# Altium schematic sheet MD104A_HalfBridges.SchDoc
size Letter; Date: Not shown in title block; ApprovedBy: Not shown in title block; CheckedBy: Not shown in title block; Author: Not shown in title block; CompanyName: Not shown in title block; Engineer: Not shown in title block; Organization: Not shown in title block; Address1: Not shown in title block; Address2: Not shown in title block; Address3: Not shown in title block; Address4: Not shown in title block; DocumentNumber: 2; Revision: Use project parameter SCH_Rev; SheetNumber: 2; SheetTotal: 5; PageSetup: Record=PageOptions¦CenterHorizontal=True¦CenterVertical=True¦PrintScale=1.00¦XCorrection=1.00¦YCorrection=1.00¦PrintKind=0¦BorderSize=5000000¦LeftOffset=0¦BottomOffset=0¦Orientation=2¦PaperLength=1000¦PaperWidth=1000¦Scale=100¦PaperSource=15¦PrintQuality=600¦MediaType=1¦DitherType=10¦PaperKind=Letter¦PrintScaleMode=1
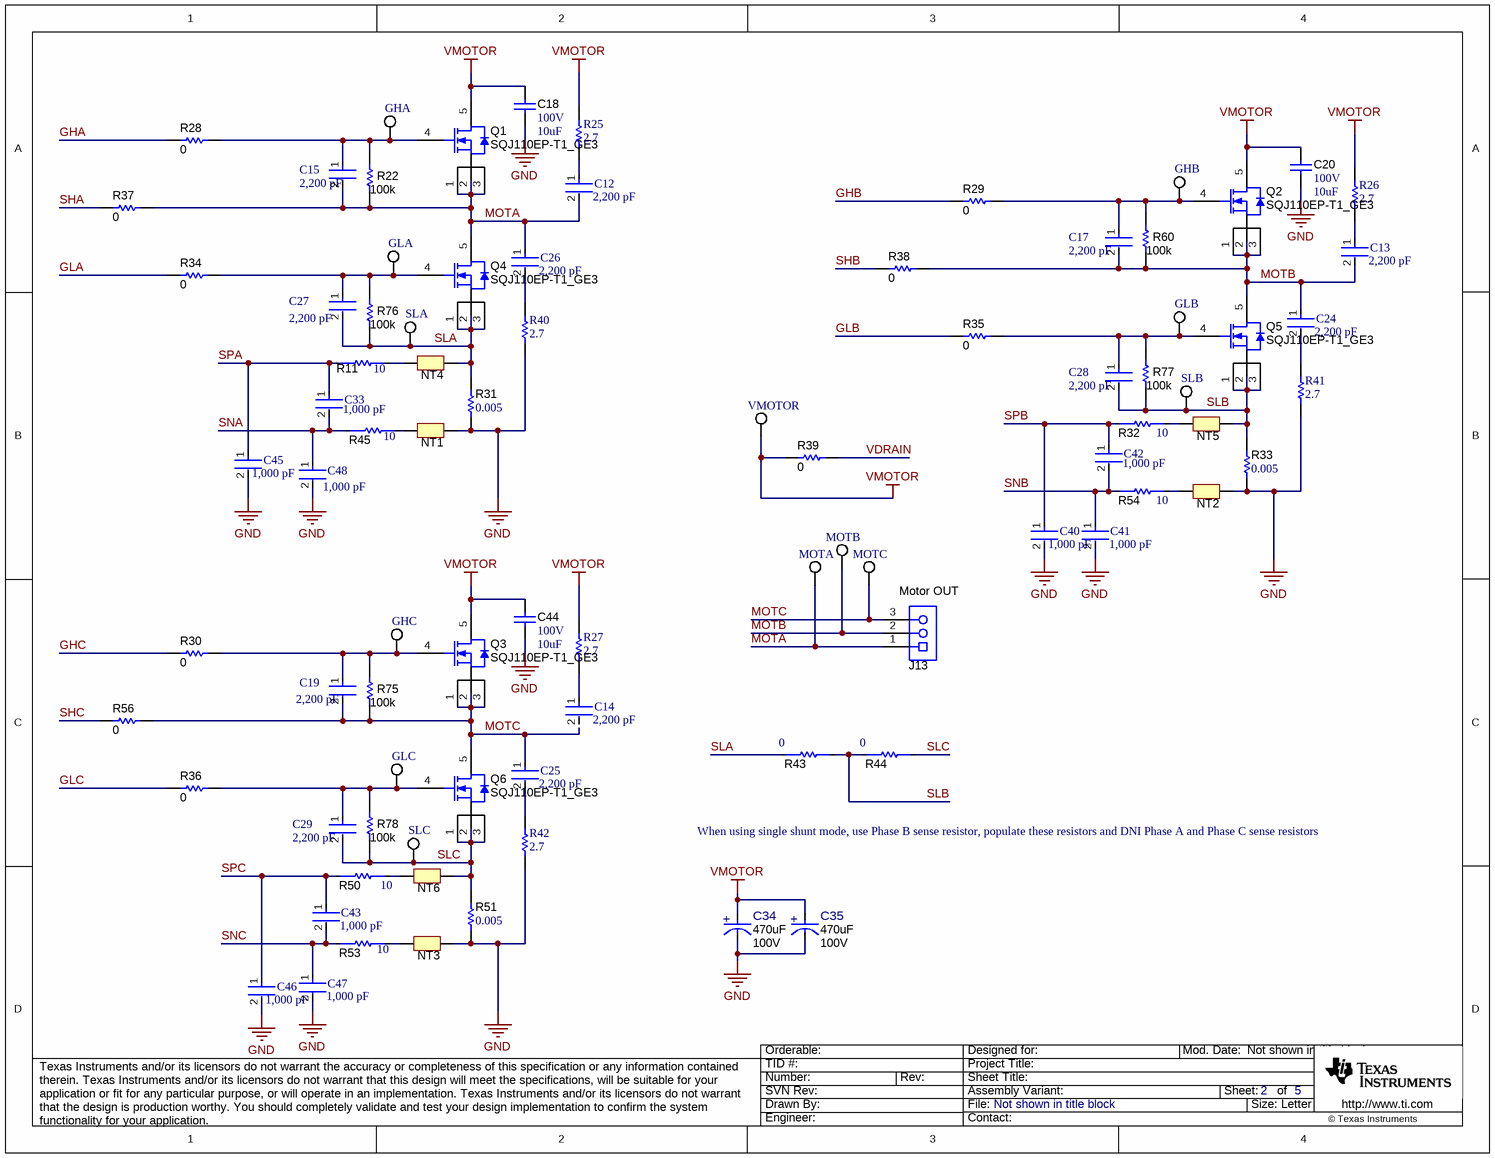
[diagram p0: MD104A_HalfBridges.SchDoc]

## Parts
C12  value 2,200 pF  [FP-C0603C-CF-MFG]  (hidden comment: C0603C222K1RACAUTO)
C13  value 2,200 pF  [FP-C0603C-CF-MFG]  (hidden comment: C0603C222K1RACAUTO)
C14  value 2,200 pF  [FP-C0603C-CF-MFG]  (hidden comment: C0603C222K1RACAUTO)
C15  value 2,200 pF  [FP-C0603C-CF-MFG]  (hidden comment: C0603C222K1RACAUTO)
C17  value 2,200 pF  [FP-C0603C-CF-MFG]  (hidden comment: C0603C222K1RACAUTO)
C18  VDC_V: 100V  ValueDisplayed: 10uF  [2220_280L]  (hidden comment: CGA9N3X7S2A106K230KE)
C19  value 2,200 pF  [FP-C0603C-CF-MFG]  (hidden comment: C0603C222K1RACAUTO)
C20  VDC_V: 100V  ValueDisplayed: 10uF  [2220_280L]  (hidden comment: CGA9N3X7S2A106K230KE)
C24  value 2,200 pF  [FP-C0603C-CF-MFG]  (hidden comment: C0603C222K1RACAUTO)
C25  value 2,200 pF  [FP-C0603C-CF-MFG]  (hidden comment: C0603C222K1RACAUTO)
C26  value 2,200 pF  [FP-C0603C-CF-MFG]  (hidden comment: C0603C222K1RACAUTO)
C27  value 2,200 pF  [FP-C0603C-CF-MFG]  (hidden comment: C0603C222K1RACAUTO)
C28  value 2,200 pF  [FP-C0603C-CF-MFG]  (hidden comment: C0603C222K1RACAUTO)
C29  value 2,200 pF  [FP-C0603C-CF-MFG]  (hidden comment: C0603C222K1RACAUTO)
C33  value 1,000 pF  [FP-C0603C-CF-MFG]  (hidden comment: C0603C102K4RACAUTO)
C34  ValueDisplayed: 470uF  VDC_V: 100V  [FP-ESH477M100AM2AA_RADIAL-MFG]  (hidden comment: ESH477M100AM2AA)
C35  ValueDisplayed: 470uF  VDC_V: 100V  [FP-ESH477M100AM2AA_RADIAL-MFG]  (hidden comment: ESH477M100AM2AA)
C40  value 1,000 pF  [FP-C0603C-CF-MFG]  (hidden comment: C0603C102K4RACAUTO)
C41  value 1,000 pF  [FP-C0603C-CF-MFG]  (hidden comment: C0603C102K4RACAUTO)
C42  value 1,000 pF  [FP-C0603C-CF-MFG]  (hidden comment: C0603C102K4RACAUTO)
C43  value 1,000 pF  [FP-C0603C-CF-MFG]  (hidden comment: C0603C102K4RACAUTO)
C44  VDC_V: 100V  ValueDisplayed: 10uF  [2220_280L]  (hidden comment: CGA9N3X7S2A106K230KE)
C45  value 1,000 pF  [FP-C0603C-CF-MFG]  (hidden comment: C0603C102K4RACAUTO)
C46  value 1,000 pF  [FP-C0603C-CF-MFG]  (hidden comment: C0603C102K4RACAUTO)
C47  value 1,000 pF  [FP-C0603C-CF-MFG]  (hidden comment: C0603C102K4RACAUTO)
C48  value 1,000 pF  [FP-C0603C-CF-MFG]  (hidden comment: C0603C102K4RACAUTO)
GHA  5015  [Testpoint_Keystone_Miniature]  (value not drawn)
GHB  5015  [Testpoint_Keystone_Miniature]  (value not drawn)
GHC  5015  [Testpoint_Keystone_Miniature]  (value not drawn)
GLA  5015  [Testpoint_Keystone_Miniature]  (value not drawn)
GLB  5015  [Testpoint_Keystone_Miniature]  (value not drawn)
GLC  5015  [Testpoint_Keystone_Miniature]  (value not drawn)
J13  Motor OUT  [Phoenix_1904150]
MOTA  5016  [Testpoint_Keystone_Compact]  (value not drawn)
MOTB  5016  [Testpoint_Keystone_Compact]  (value not drawn)
MOTC  5016  [Testpoint_Keystone_Compact]  (value not drawn)
NT1  Net-Tie  [Net-Tie_10mil]  (value not drawn)  (net tie, no BOM)
NT2  Net-Tie  [Net-Tie_10mil]  (value not drawn)  (net tie, no BOM)
NT3  Net-Tie  [Net-Tie_10mil]  (value not drawn)  (net tie, no BOM)
NT4  Net-Tie  [Net-Tie_10mil]  (value not drawn)  (net tie, no BOM)
NT5  Net-Tie  [Net-Tie_10mil]  (value not drawn)  (net tie, no BOM)
NT6  Net-Tie  [Net-Tie_10mil]  (value not drawn)  (net tie, no BOM)
Q1  SQJ110EP-T1_GE3  [PowerPAK_SO-8L]
Q2  SQJ110EP-T1_GE3  [PowerPAK_SO-8L]
Q3  SQJ110EP-T1_GE3  [PowerPAK_SO-8L]
Q4  SQJ110EP-T1_GE3  [PowerPAK_SO-8L]
Q5  SQJ110EP-T1_GE3  [PowerPAK_SO-8L]
Q6  SQJ110EP-T1_GE3  [PowerPAK_SO-8L]
R11  value 10  [FP-CPF-A-0603B10RE_0603-MFG]  (hidden comment: CPF-A-0603B10RE)
R22  ValueDisplayed: 100k  [0603L]  (hidden comment: CRCW0603100KFKEA)
R25  2.7  [RESC1608X55X30LL20T10]
R26  2.7  [RESC1608X55X30LL20T10]
R27  2.7  [RESC1608X55X30LL20T10]
R28  ValueDisplayed: 0  [0603L]  (hidden comment: RCS06030000Z0EA)
R29  ValueDisplayed: 0  [0603L]  (hidden comment: RCS06030000Z0EA)
R30  ValueDisplayed: 0  [0603L]  (hidden comment: RCS06030000Z0EA)
R31  ValueDisplayed: 0.005  [CRE2512-R5_R9]  (hidden comment: CRE2512-FZ-R005E-3)
R32  value 10  [FP-CPF-A-0603B10RE_0603-MFG]  (hidden comment: CPF-A-0603B10RE)
R33  ValueDisplayed: 0.005  [CRE2512-R5_R9]  (hidden comment: CRE2512-FZ-R005E-3)
R34  ValueDisplayed: 0  [0603L]  (hidden comment: RCS06030000Z0EA)
R35  ValueDisplayed: 0  [0603L]  (hidden comment: RCS06030000Z0EA)
R36  ValueDisplayed: 0  [0603L]  (hidden comment: RCS06030000Z0EA)
R37  ValueDisplayed: 0  [0603L]  (hidden comment: RCS06030000Z0EA)
R38  ValueDisplayed: 0  [0603L]  (hidden comment: RCS06030000Z0EA)
R39  ValueDisplayed: 0  [0603L]  (hidden comment: RCS06030000Z0EA)
R40  2.7  [RESC1608X55X30LL20T10]
R41  2.7  [RESC1608X55X30LL20T10]
R42  2.7  [RESC1608X55X30LL20T10]
R43  value 0  [FP-CRCW12060000Z0EAC_1206-MFG]  (hidden comment: CRCW12060000Z0EAC)
R44  value 0  [FP-CRCW12060000Z0EAC_1206-MFG]  (hidden comment: CRCW12060000Z0EAC)
R45  value 10  [FP-CPF-A-0603B10RE_0603-MFG]  (hidden comment: CPF-A-0603B10RE)
R50  value 10  [FP-CPF-A-0603B10RE_0603-MFG]  (hidden comment: CPF-A-0603B10RE)
R51  ValueDisplayed: 0.005  [CRE2512-R5_R9]  (hidden comment: CRE2512-FZ-R005E-3)
R53  value 10  [FP-CPF-A-0603B10RE_0603-MFG]  (hidden comment: CPF-A-0603B10RE)
R54  value 10  [FP-CPF-A-0603B10RE_0603-MFG]  (hidden comment: CPF-A-0603B10RE)
R56  ValueDisplayed: 0  [0603L]  (hidden comment: RCS06030000Z0EA)
R60  ValueDisplayed: 100k  [0603L]  (hidden comment: CRCW0603100KFKEA)
R75  ValueDisplayed: 100k  [0603L]  (hidden comment: CRCW0603100KFKEA)
R76  ValueDisplayed: 100k  [0603L]  (hidden comment: CRCW0603100KFKEA)
R77  ValueDisplayed: 100k  [0603L]  (hidden comment: CRCW0603100KFKEA)
R78  ValueDisplayed: 100k  [0603L]  (hidden comment: CRCW0603100KFKEA)
SLA  5015  [Testpoint_Keystone_Miniature]  (value not drawn)
SLB  5015  [Testpoint_Keystone_Miniature]  (value not drawn)
SLC  5015  [Testpoint_Keystone_Miniature]  (value not drawn)
VMOTOR  5016  [Testpoint_Keystone_Compact]  (value not drawn)

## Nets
GND: C18.2 C20.2 C34.1(CATHODE) C35.1(CATHODE) C40.2 C41.2 C44.2 C45.2 C46.2 C47.2 C48.2 NT1.2 NT2.2 NT3.2 R31.1 R33.1 R40.1 R41.1 R42.1 R51.1
VMOTOR: C18.1 C20.1 C34.2(ANODE) C35.2(ANODE) C44.1 Q1.5(D) Q2.5(D) Q3.5(D) R25.2 R26.2 R27.2 R39.2 VMOTOR.1
GHA: R28.1
GHB: R29.1
GHC: R30.1
GLA: R34.1
GLB: R35.1
GLC: R36.1
MOTA: C12.2 C15.2 C26.1 J13.1 MOTA.1 Q1.1(S) Q1.2(S) Q1.3(S) Q4.5(D) R22.2 R37.2
MOTB: C13.2 C17.2 C24.1 J13.2 MOTB.1 Q2.1(S) Q2.2(S) Q2.3(S) Q5.5(D) R38.2 R60.2
MOTC: C19.2 C25.1 J13.3 MOTC.1 Q3.1(S) Q3.2(S) Q3.3(S) Q6.5(D) R56.2 R75.2
SHA: R37.1
SHB: R38.1
SHC: R56.1
SLA: C27.2 NT4.2 Q4.1(S) Q4.2(S) Q4.3(S) R31.2 R43.1 R76.2 SLA.1
SLB: C28.2 NT5.2 Q5.1(S) Q5.2(S) Q5.3(S) R33.2 R43.2 R44.1 R77.2 SLB.1
SLC: C29.2 NT6.2 Q6.1(S) Q6.2(S) Q6.3(S) R44.2 R51.2 R78.2 SLC.1
SNA: C33.2 C48.1 R45.1
SNB: C41.1 C42.2 R54.1
SNC: C43.2 C47.1 R53.1
SPA: C33.1 C45.1 R11.1
SPB: C40.1 C42.1 R32.1
SPC: C43.1 C46.1 R50.1
VDRAIN: R39.1
NetC12_1: C12.1 R25.1
NetC13_1: C13.1 R26.1
NetC14_1: C14.1 R27.1
NetC15_1: C15.1 GHA.1 Q1.4(G) R22.1 R28.2
NetC17_1: C17.1 GHB.1 Q2.4(G) R29.2 R60.1
NetC19_1: C19.1 GHC.1 Q3.4(G) R30.2 R75.1
NetC24_2: C24.2 R41.2
NetC25_2: C25.2 R42.2
NetC26_2: C26.2 R40.2
NetC27_1: C27.1 GLA.1 Q4.4(G) R34.2 R76.1
NetC28_1: C28.1 GLB.1 Q5.4(G) R35.2 R77.1
NetC29_1: C29.1 GLC.1 Q6.4(G) R36.2 R78.1
NetNT1_1: NT1.1 R45.2
NetNT2_1: NT2.1 R54.2
NetNT3_1: NT3.1 R53.2
NetNT4_1: NT4.1 R11.2
NetNT5_1: NT5.1 R32.2
NetNT6_1: NT6.1 R50.2

Not connected (* = marked no-connect by the designer): C14 2

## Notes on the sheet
- When using single shunt mode, use Phase B sense resistor, populate these resistors and DNI Phase A and Phase C sense resistors

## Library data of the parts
C12-C15 C17 C19 C24-C29 = CMP-03020-029902-1: CAP CER 2200PF 100V X7R 0603; Manufacturer: KEMET; Temperature Coefficient: 30ppm/°C; Automotive Grade: Grade 1; Tolerance: 0.1; Material: Ceramic
C18 C20 C44 = CMP-0064964-2: CAP, CERM, 10 uF, 100 V,+/- 10%, X7S, AEC-Q200 Grade 1, 2220; Manufacturer: TDK; TaMin_C: -55°C; Polarized: N; SizeAreaWB_mm2: 53.9; Value1: Unknown; U/M: EA; Value: 10uF; TaMax_C: 125°C; SizeZ_mm: 2.8; SizeX_mm: 5.7; SizeY_mm: 5; Cap_Case: 2220; SizeArea_mm2: 28.5; AEC Qualified: Y; Cap_F: 10µF; AEC Grade: 1; AEC Category: Q200
C33 C40-C43 C45-C48 = CMP-03020-019178-1: CAP CER SMD 0603 1000PF 10% X7R C0603C102K4RACAUTO; Manufacturer: KEMET; Temperature Coefficient: 30ppm/°C; Voltage Rating: 16 V; Material: Ceramic; Tolerance: 0.1; Automotive Grade: Grade 1
C34 C35 = CMP-0120361-1: 470 µF 100 V Aluminum Electrolytic Capacitors Radial, Can 2000 Hrs @ 105°C; Manufacturer: KEMET; AEC Qualified: No; Cap_F: 470µF; IRMS_A: 875mA; SizeZ_mm: 34mm; Tolerance_%: 20%; Dissipation Factor: 10%; Leakage Current: 470uA; Life: 2000Hours; Value: 470µF
GHA GHB GHC GLA GLB GLC SLA SLB SLC = CMP-0055152-2: Test Point, Miniature, SMT; Manufacturer: Keystone Electronics; CT: TRUE; Green_Lifecycle: Active; Green_REACh: Passed; CNHeader: FALSE
J13 = CMP-0055528-1: Terminal Block, 9.52mm, 3x1, R/A, TH; PartNumber: 1904150; Manufacturer: Phoenix Contact; Pitch_mm: 9.52; Gender: Female; Row_Count: 1; Current_A: 32A; Voltage_V: 1kV; Cert_UL: Y; CNHeader: FALSE; CT: TRUE
MOTA MOTB MOTC VMOTOR = CMP-0055153-2: Test Point, Compact, SMT; Manufacturer: Keystone Electronics; Green_Lifecycle: Active; Green_REACh: Passed; CNHeader: FALSE; CT: TRUE
NT1-NT6 = CMP-0078142-6: Single point connection between nets.
Q1-Q6 = CMP-0001028-3: MOSFET, N-CH, 100 V, 170 A, AEC-Q101, PowerPAK_SO-8L; PartNumber: SQJ456EP-T1_GE3; Alternate Manufacturer: None; Manufacturer: Vishay-Siliconix; SizeZ_mm: 1.14; ChType: N; Value2: 42 nC; VdsMax_V: 100V; SizeX_mm: 6.15; SizeY_mm: 5.13; Vgs_V: 20V; AEC Qualified: Y; Value: 100V; SizeArea_mm2: 31.5495; AEC Category: Q101; IdsMax_A: 170; SizeAreaWB_mm2: 58.1095; U/M: EA; QgTyp_nC: 42
R11 R32 R45 R50 R53 R54 = CMP-0097543-1: 10 Ohms ±0.1% 0.063W, 1/16W Chip Resistor 0603 (1608 Metric) Anti-Sulfur, Automotive AEC-Q200, Moisture Resistant Thin Film; Manufacturer: TE Connectivity; VDC_V: 50V; AEC Grade: Grade 0; AEC Qualified: Yes; TempCo: 25ppm/°C; SizeZ_mm: 0.55mm; Power_W: 62.5mW
R22 R60 R75-R78 = CMP-0021990-4: RES, 100 k, 1%, 0.1 W, AEC-Q200 Grade 0, 0603; Manufacturer: Vishay-Dale; Power_W: 100mW; TempCo: 100 ppm/C; Value: 100k; EIA_Code: E96; SizeX_mm: 1.6; SizeY_mm: 0.8; SizeZ_mm: 1; Value2: 0.1W; SizeArea_mm2: 1.28; AEC Qualified: Y; VDC_V: 75V; AEC Category: Q200; AEC Grade: 0
R25-R27 R40-R42 = CMP-2000-01928-1: 2.7, 0.125W, 0603, AEC-Q200; Manufacturer: KOA Speer; Part Number: RK73B1JTTD2R7J
R28-R30 R34-R39 R56 = CMP-0081973-1: RES, 0, 0%, 0.25 W, AEC-Q200 Grade 0, 0603; Manufacturer: Vishay-Dale; SizeAreaWB_mm2: 4.68; SizeArea_mm2: 1.28; AEC Qualified: Y; AEC Category: Q200; Value: 0; SizeZ_mm: 1; SizeY_mm: 0.8; Power_W: 250mW; Value2: 0.25W; SizeX_mm: 1.6
R31 R33 R51 = CMP-0015751-2: RES, 0.005, 1%, 3 W, AEC-Q200 Grade 0, 2512; Manufacturer: Bourns; Power_W: 3W; TempCo: 75 ppm/C; Value_Code: 5L000; U/M: EA; Value: 0.005; EIA_Code: E96; Res_ohm: 5m; SizeX_mm: 6.45; SizeY_mm: 3.35; SizeZ_mm: 0.9; SizeArea_mm2: 21.6075; AEC Qualified: Y; AEC Grade: 0; AEC Category: Q200
R43 R44 = CMP-0094724-1: Jumper 0.25W, 1/4W Chip Resistor 1206 (3216 Metric) - Thick Film; Manufacturer: Vishay; SizeZ_mm: 0.65mm; Power_W: 250mW; VDC_V: 200V; AEC Qualified: No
